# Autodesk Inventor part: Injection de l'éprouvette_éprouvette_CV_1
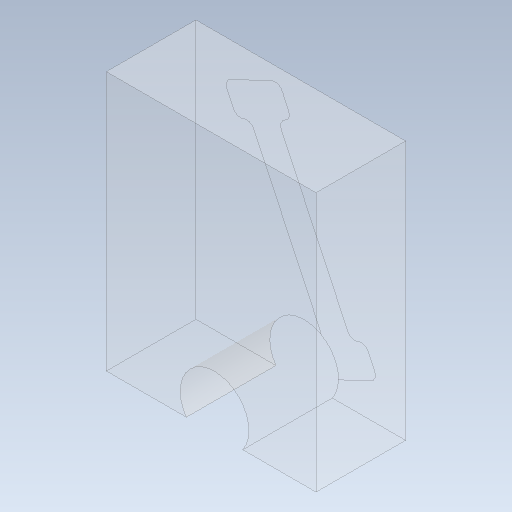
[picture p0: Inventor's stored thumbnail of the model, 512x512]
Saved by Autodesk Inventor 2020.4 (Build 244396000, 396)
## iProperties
Created: 2021-10
Part Number: Injection de l'éprouvette_éprouvette_CV_1
Material: Générique
Document SubType Name: Modeling
Designer: mel
Density: 1 g/cm^3
Appearance: Par défaut
Author: mel
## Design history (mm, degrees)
node "Injection de l'éprouvette_éprouvette_CV_Base"
feature "Sculpter2"
feature "Solide1::Injection de l'éprouvette_éprouvette_CV_Base"
tag "FonctionRepérage1"
node "Solide1"
feature "Injection de l'éprouvette_éprouvette_CV_Base_Corps"
feature "Surface2"
body "Srf2"
